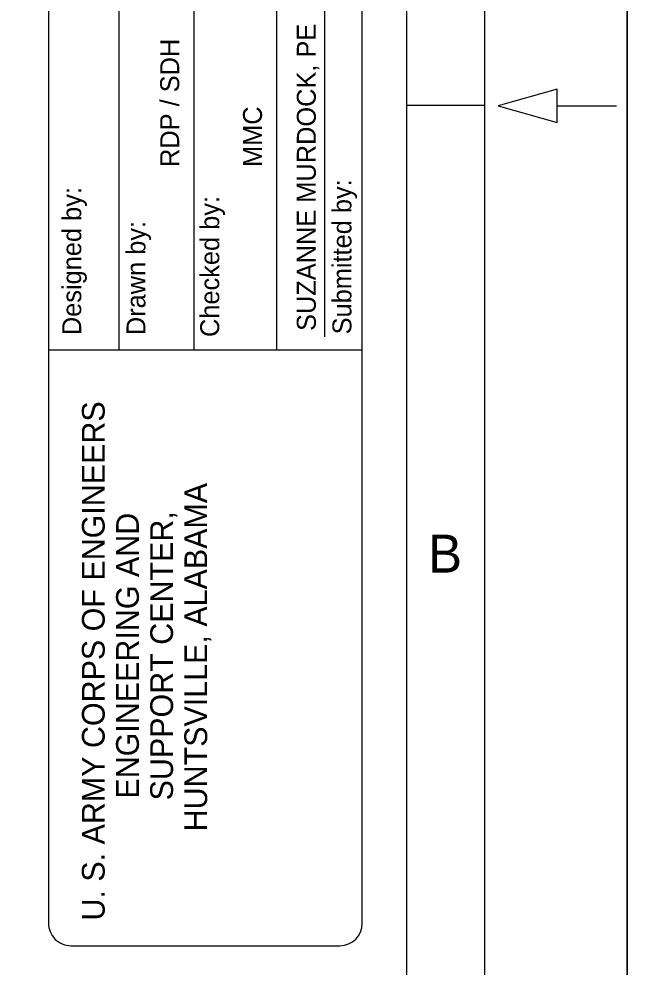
# Model space of a CAD drawing. Extents: x -0.04 to 2.79, y -0.02 to 1.81.
# Drawn here: x 2.5246 to 2.7917, y 0.5127 to 0.9292 of the extents above; entities that cross this region are included whole.
import ezdxf

# ---------------------------------------------------------------- set-up
doc = ezdxf.new("R2010")
doc.units = 0
for name, color, linetype in [('G-ANNO-NPLT', 7, 'Continuous'), ('G-ANNO-PLOT', 7, 'Continuous'), ('G-ANNO-TTLB', 7, 'Continuous')]:
    doc.layers.add(name, color=color, linetype=linetype)

msp = doc.modelspace()

# ---------------------------------------------------------------- linework, layer by layer
at = {"layer": 'G-ANNO-NPLT'}
msp.add_lwpolyline([(-0.04167, 1.8125), (2.79167, 1.8125), (2.79167, -0.02083), (-0.04167, -0.02083)], close=True, dxfattribs=at)
at = {"layer": 'G-ANNO-PLOT'}
msp.add_line((2.79167, 1.8125), (2.79167, -0.02083), dxfattribs=at)
msp.add_lwpolyline([(0, 0), (2.79167, 0), (2.79167, 1.79167), (0, 1.79167)], close=True, dxfattribs=at)
at = {"layer": 'G-ANNO-TTLB'}
for p, q in [((2.63771, 1.13212), (2.63771, 0.78365)), ((2.65896, 0.78952), (2.65896, 1.12584)), ((2.56849, 0.97595), (2.56849, 0.78365)), ((2.60138, 0.97595), (2.60138, 0.78365)), ((2.69501, 0.89138), (2.72917, 0.89138)), ((2.76095, 0.89101), (2.78699, 0.89101)), ((2.67536, 0.78365), (2.53757, 0.78365)), ((2.54741, 0.52206), (2.66552, 0.52206))]:
    msp.add_line(p, q, dxfattribs=at)
for points in [[(0.08333, 0.04167), (2.72917, 0.04167), (2.72917, 1.75), (0.2515, 1.75)], [(0.11656, 0.08028), (2.69501, 0.08028), (2.69501, 1.71305), (0.11656, 1.71305)], [(2.53757, 1.12228), (2.53757, 0.53206)], [(2.67536, 0.53191), (2.67536, 1.12228)]]:
    msp.add_lwpolyline(points, dxfattribs=at)
msp.add_lwpolyline([(2.76095, 0.89833), (2.73503, 0.89101), (2.76095, 0.88369)], close=True, dxfattribs=at)
for centre, major_axis, start_param, end_param in [((2.54741, 0.53191), (-0.00984, 0), 6.267222, 7.853982), ((2.66552, 0.53191), (0.00984, 0), 4.712389, 6.283185)]:
    msp.add_ellipse(centre, major_axis=major_axis, ratio=0.999936, start_param=start_param, end_param=end_param, dxfattribs=at)

# ---------------------------------------------------------------- texts
for s, height, p in [('Submitted by:                                                                 Date', 0.0083333, (2.67061, 0.79063)), ('SUZANNE MURDOCK, PE', 0.0083333, (2.65496, 0.79214)), ('RDP / SDH', 0.008333, (2.59496, 0.86417)), ('MMC', 0.008333, (2.63134, 0.86417)), ('Designed by:', 0.0083333, (2.55193, 0.7903)), ('Checked by:', 0.0083333, (2.61254, 0.78948)), ('Drawn by:', 0.008333, (2.58014, 0.7903)), ('U. S. ARMY CORPS OF ENGINEERS', 0.01, (2.56225, 0.53311)), ('HUNTSVILLE, ALABAMA', 0.01, (2.60725, 0.5723)), ('ENGINEERING AND', 0.01, (2.57725, 0.58668)), ('SUPPORT CENTER,', 0.01, (2.59225, 0.5859))]:
    msp.add_text(s, height=height, rotation=90, dxfattribs=at).set_placement(p)
msp.add_text('B', height=0.01667, dxfattribs=at).set_placement((2.70433, 0.68597))

doc.saveas('drawing.dxf')
